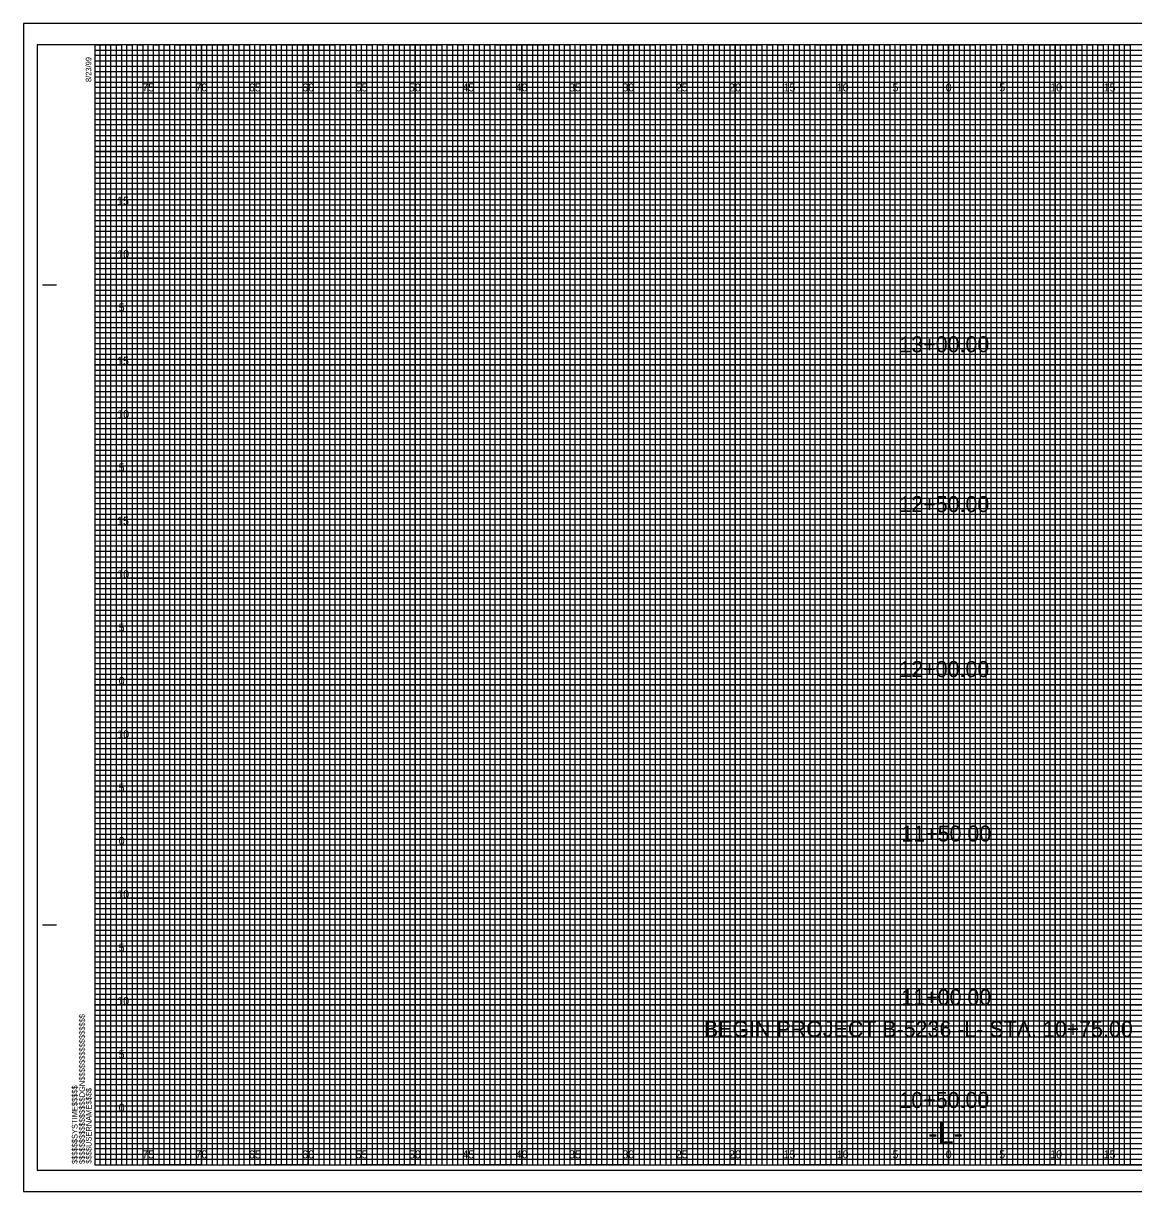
# Model space of a CAD drawing. Extents: x -7 to 162, y -2 to 107.
# Drawn here: x -6.7 to 97.3, y -2.5 to 107 of the extents above; entities that cross this region are included whole.
import ezdxf

# ---------------------------------------------------------------- set-up
doc = ezdxf.new("R2010")
doc.units = 0
for name, color, linetype in [('Prop XS Alignment Label', 7, 'Continuous'), ('Prop XS Elevation Labels', 7, 'Continuous'), ('Prop XS Offset Labels', 7, 'Continuous'), ('Prop XS Station Labels', 7, 'Continuous'), ('Sheet Cross Section CELL', 7, 'Continuous'), ('Sheet Cross Section Grid Major CELL', 7, 'Continuous'), ('Sheet Cross Section Grid Middle CELL', 7, 'Continuous'), ('Sheet Cross Section Grid Minor 1 CELL', 7, 'Continuous'), ('Sheet Cross Section Grid Minor 2 CELL', 7, 'Continuous'), ('Sheet Cutting Line CELL', 7, 'Continuous'), ('Sheet DOT Grid CELL', 7, 'Continuous'), ('Sheet Plot Border Inside CELL', 7, 'Continuous'), ('Sheet Plot Border Outside CELL', 7, 'Continuous')]:
    doc.layers.add(name, color=color, linetype=linetype)

msp = doc.modelspace()

# ---------------------------------------------------------------- linework, layer by layer
at = {"layer": 'Sheet Cross Section CELL'}
for p, q in [((-4.9, 82.5), (-3.65, 82.5)), ((-4.85, 82.5), (-3.6, 82.5)), ((-4.9, 22.5), (-3.65, 22.5)), ((-4.85, 22.5), (-3.6, 22.5)), ((0, 0), (0, 0)), ((0, 0), (0, 0)), ((0, 0), (0, 0)), ((0, 0), (0, 0)), ((0, 0), (0, 0)), ((0, 0), (0, 0)), ((0, 0), (0, 0))]:
    msp.add_line(p, q, dxfattribs=at)
msp.add_lwpolyline([(160, 105), (0, 105), (0, 0), (160, 0)], close=True, dxfattribs=at)
at = {"layer": 'Sheet Cross Section Grid Major CELL'}
for p, q in [((5, 105), (0, 105)), ((5, 0), (5, 105)), ((15, 105), (10, 105)), ((10, 105), (10, 0)), ((15, 0), (15, 105)), ((25, 105), (20, 105)), ((20, 105), (20, 0)), ((25, 0), (25, 105)), ((35, 105), (30, 105)), ((30, 105), (30, 0)), ((35, 0), (35, 105)), ((45, 105), (40, 105)), ((40, 105), (40, 0)), ((45, 0), (45, 105)), ((55, 105), (50, 105)), ((50, 105), (50, 0)), ((55, 0), (55, 105)), ((65, 105), (60, 105)), ((60, 105), (60, 0)), ((65, 0), (65, 105)), ((75, 105), (70, 105)), ((70, 105), (70, 0)), ((75, 0), (75, 105)), ((85, 105), (80, 105)), ((80, 105), (80, 0)), ((85, 0), (85, 105)), ((95, 105), (90, 105)), ((90, 105), (90, 0)), ((95, 0), (95, 105)), ((10, 0), (5, 0)), ((20, 0), (15, 0)), ((30, 0), (25, 0)), ((40, 0), (35, 0)), ((50, 0), (45, 0)), ((60, 0), (55, 0)), ((70, 0), (65, 0)), ((80, 0), (75, 0)), ((90, 0), (85, 0)), ((100, 0), (95, 0))]:
    msp.add_line(p, q, dxfattribs=at)
for points in [[(0, 100), (160, 100), (160, 95), (0, 95)], [(0, 90), (160, 90), (160, 85), (0, 85)], [(0, 80), (160, 80), (160, 75), (0, 75)], [(0, 70), (160, 70), (160, 65), (0, 65)], [(0, 60), (160, 60), (160, 55), (0, 55)], [(0, 50), (160, 50), (160, 45), (0, 45)], [(0, 40), (160, 40), (160, 35), (0, 35)], [(0, 30), (160, 30), (160, 25), (0, 25)], [(0, 20), (160, 20), (160, 15), (0, 15)], [(0, 10), (160, 10), (160, 5), (0, 5)]]:
    msp.add_lwpolyline(points, dxfattribs=at)
at = {"layer": 'Sheet Cross Section Grid Middle CELL'}
for points in [[(0, 105), (2.5, 105), (2.5, 0), (7.5, 0), (7.5, 105), (12.5, 105), (12.5, 0), (17.5, 0), (17.5, 105), (22.5, 105), (22.5, 0), (27.5, 0), (27.5, 105), (32.5, 105), (32.5, 0), (37.5, 0), (37.5, 105), (42.5, 105), (42.5, 0), (47.5, 0), (47.5, 105), (52.5, 105), (52.5, 0), (57.5, 0), (57.5, 105), (62.5, 105), (62.5, 0), (67.5, 0), (67.5, 105), (72.5, 105), (72.5, 0), (77.5, 0), (77.5, 105), (82.5, 105), (82.5, 0), (87.5, 0), (87.5, 105), (92.5, 105), (92.5, 0), (97.5, 0)], [(0, 102.5), (137.5, 102.5)], [(0, 92.5), (160, 92.5), (160, 97.5), (0, 97.5)], [(0, 82.5), (160, 82.5), (160, 87.5), (0, 87.5)], [(0, 72.5), (160, 72.5), (160, 77.5), (0, 77.5)], [(0, 62.5), (160, 62.5), (160, 67.5), (0, 67.5)], [(0, 52.5), (160, 52.5), (160, 57.5), (0, 57.5)], [(0, 42.5), (160, 42.5), (160, 47.5), (0, 47.5)], [(0, 32.5), (160, 32.5), (160, 37.5), (0, 37.5)], [(0, 22.5), (160, 22.5), (160, 27.5), (0, 27.5)], [(0, 12.5), (160, 12.5), (160, 17.5), (0, 17.5)], [(0, 2.5), (160, 2.5), (160, 7.5), (0, 7.5)]]:
    msp.add_lwpolyline(points, dxfattribs=at)
at = {"layer": 'Sheet Cross Section Grid Minor 1 CELL'}
for p, q in [((0, 104.5), (130, 104.5)), ((130, 103.99), (0, 103.99)), ((0, 103.99), (0, 103.5)), ((0, 103.5), (130, 103.5)), ((130, 102.95), (0, 102.95)), ((0, 102.95), (0, 102)), ((0, 102), (160, 102))]:
    msp.add_line(p, q, dxfattribs=at)
for points in [[(0, 101.5), (135, 101.5), (160, 101.5), (160, 101), (0, 101)], [(0, 100.5), (160, 100.5), (160, 99.5), (0, 99.5)], [(0, 99), (160, 99), (160, 98.5), (0, 98.49)], [(0, 98), (160, 98), (160, 97), (0, 97)], [(0, 96.5), (160, 96.5), (160, 96), (0, 96)], [(0, 95.5), (160, 95.5), (160, 94.5), (0, 94.5)], [(0, 94), (160, 94), (160, 93.5), (0, 93.5)], [(0, 93), (160, 93), (160, 92), (0, 92)], [(0, 91.5), (160, 91.5), (160, 91), (0, 91)], [(0, 90.5), (160, 90.5), (160, 89.5), (0, 89.5)], [(0, 89), (160, 89), (160, 88.5), (0, 88.5)], [(0, 88), (160, 88), (160, 86.98), (160, 86.5), (160, 86), (0, 86)], [(0, 87), (160, 87), (160, 86.5), (0, 86.5)], [(0, 85.5), (160, 85.5), (160, 84.5), (0, 84.52)], [(0, 84.52), (160, 84.5), (160, 84), (0, 84)], [(0, 83.5), (160, 83.5), (160, 83), (0, 83)], [(0, 82), (160, 82), (160, 81.5), (0, 81.5)], [(0, 81), (160, 81), (160, 80.5), (0, 80.5)], [(-0.04, 79.45), (160, 79.45), (160, 78.94), (-0.04, 78.94)], [(0, 78.5), (160, 78.5), (160, 78), (0, 78)], [(0, 77), (160, 77), (160, 76.5), (0, 76.5)], [(0, 76), (160, 76), (160, 75.5), (0, 75.5)], [(0, 74.5), (160, 74.5), (160, 74), (0, 74)], [(0, 73.5), (160, 73.5), (160, 73), (0, 73)], [(0, 72), (160, 72), (160, 71.5), (0, 71.5)], [(0, 71), (160, 71), (160, 70.5), (0, 70.5)], [(0, 69.5), (160, 69.5), (160, 68.99), (0, 69)], [(0, 68.5), (160, 68.5), (160, 68), (0, 68)], [(0, 67), (160, 67), (160, 66.5), (0, 66.5)], [(0, 66), (160, 66), (160, 65.5), (0, 65.5)], [(0, 64.5), (160, 64.5), (160, 64), (0, 64)], [(0, 63.5), (160, 63.5), (160, 63), (0, 63)], [(0, 62), (160, 62), (160, 61.5), (0, 61.5)], [(0, 61), (160, 61), (160, 60.5), (0, 60.5)], [(0, 59.5), (160, 59.5), (160, 59), (0, 59)], [(0, 58.5), (160.03, 58.45), (160, 58), (0, 58)], [(0, 57), (160, 57), (160, 56.5), (0, 56.5)], [(0, 56), (160, 56), (160, 55.5), (0, 55.5)], [(0, 54.5), (160, 54.5), (160, 54), (0, 54)], [(0, 53.5), (160, 53.5), (160, 53), (0, 53)], [(0, 52), (160, 52), (160, 51.5), (0, 51.5)], [(0, 51), (160, 51), (160, 50.5), (0, 50.5)], [(0, 49.5), (160, 49.5), (160, 49), (0, 49)], [(0, 48.5), (160, 48.5), (160, 48), (0, 48)], [(0, 47), (160, 47), (160, 46.5), (0, 46.5)], [(0, 46), (160, 46), (160, 45.5), (0, 45.5)], [(0, 44.5), (160, 44.5), (160, 44), (0, 44)], [(0, 43.5), (160, 43.5), (160, 43), (0, 43)], [(0, 42), (160, 42), (160, 41.5), (0, 41.5)], [(0, 41), (160, 41), (160, 40.5), (0, 40.5)], [(0, 39.5), (160, 39.5), (160, 38.99), (0, 39)], [(0, 38.5), (160, 38.5), (160, 38), (0, 38)], [(0, 37), (160, 37), (160, 36.5), (0, 36.5)], [(0, 36), (160, 36), (160, 35.5), (0, 35.5)], [(0, 34.5), (160, 34.5), (160, 34), (0, 34)], [(0, 33.5), (160, 33.5), (160, 33), (0, 33)], [(0, 32), (160, 32), (160, 31.5), (0, 31.5)], [(0, 31), (160, 31), (160, 30.5), (0, 30.5)], [(0, 29.5), (160, 29.5), (160, 29), (0, 29)], [(0, 28.5), (160.03, 28.46), (160, 28), (0, 28)], [(0, 27), (160, 27), (160, 26.5), (0, 26.5)], [(0, 26), (160, 26), (160, 25.5), (0, 25.5)], [(0, 24.5), (160, 24.5), (160, 24), (0, 24)], [(0, 23.5), (160, 23.5), (160, 23), (0, 23)], [(0, 22), (160, 22), (160, 21.5), (0, 21.5)], [(0, 21), (160, 21), (160, 20.5), (0, 20.5)], [(0, 19.5), (160, 19.5), (160, 19), (0, 19)], [(0, 18.5), (160, 18.5), (160, 18), (0, 18)], [(0, 17), (160, 17), (160, 16.5), (0, 16.5)], [(0, 16), (160, 16), (160, 15.5), (0, 15.5)], [(0, 14.5), (160, 14.5), (160, 14), (0, 14)], [(0, 13.5), (160, 13.5), (160, 13), (0, 13)], [(0, 12), (160, 12), (160, 11.5), (0, 11.5)], [(0, 11), (160, 11), (160, 10.5), (0, 10.5)], [(0, 9.5), (160, 9.5), (160, 9), (0, 9)], [(0, 8.5), (160, 8.5), (160, 8), (0, 8)], [(0, 7), (160, 7), (160, 6.5), (0, 6.5)], [(0, 6), (160, 6), (160, 5.5), (0, 5.5)], [(0, 4.5), (160, 4.5), (160, 4), (0, 4)], [(0, 3.5), (160, 3.5), (160, 3), (0, 3)], [(0, 2), (160, 2), (160, 1.5), (0, 1.5)], [(0, 1), (160, 1), (160, 0.5), (0, 0.5)]]:
    msp.add_lwpolyline(points, dxfattribs=at)
at = {"layer": 'Sheet Cross Section Grid Minor 2 CELL'}
for points in [[(0, 0), (0.5, 0), (0.5, 105), (1, 105), (1, 0)], [(1, 0), (1.5, 0), (1.5, 105), (2, 105), (2, 0)], [(2.5, 0), (3, 0), (3, 105), (3.5, 105), (3.5, 0)], [(3.5, 0), (4, 0), (4, 105), (4.5, 105), (4.5, 0)], [(5, 0), (5.5, 0), (5.5, 105), (6, 105), (6, 0)], [(6, 0), (6.5, 0), (6.5, 105), (7, 105), (7, 0)], [(7.5, 0), (8, 0), (8, 105), (8.5, 105), (8.5, 0)], [(8.5, 0), (9, 0), (9, 105), (9.5, 105), (9.5, 0)], [(10, 0), (10.5, 0), (10.5, 105), (11, 105), (11, 0)], [(11, 0), (11.5, 0), (11.5, 105), (12, 105), (12, 0)], [(12.5, 0), (13, 0), (13, 105), (13.5, 105), (13.5, 0)], [(13.5, 0), (14, 0), (14, 105), (14.5, 105), (14.5, 0)], [(15, 0), (15.5, 0), (15.5, 105), (16, 105), (16, 0)], [(16, 0), (16.5, 0), (16.5, 105), (17, 105), (17, 0)], [(17.5, 0), (18, 0), (18, 105), (18.5, 105), (18.5, 0)], [(18.5, 0), (19, 0), (19, 105), (19.5, 105), (19.5, 0)], [(20, 0), (20.5, 0), (20.5, 105), (21, 105), (21, 0)], [(21, 0), (21.5, 0), (21.5, 105), (22, 105), (22, 0)], [(22.5, 0), (23, 0), (23, 105), (23.5, 105), (23.5, 0)], [(23.5, 0), (24, 0), (24, 105), (24.5, 105), (24.5, 0)], [(25, 0), (25.5, 0), (25.5, 105), (26, 105), (26, 0)], [(26, 0), (26.5, 0), (26.5, 105), (27, 105), (27, 0)], [(27.5, 0), (28, 0), (28, 105), (28.5, 105), (28.5, 0)], [(28.5, 0), (29, 0), (29, 105), (29.5, 105), (29.5, 0)], [(30, 0), (30.5, 0), (30.5, 105), (31, 105), (31, 0)], [(31, 0), (31.5, 0), (31.5, 105), (32, 105), (32, 0)], [(32.5, 0), (33, 0), (33, 105), (33.5, 105), (33.5, 0)], [(33.5, 0), (34, 0), (34, 105), (34.5, 105), (34.5, 0)], [(35, 0), (35.5, 0), (35.5, 105), (36, 105), (36, 0)], [(36, 0), (36.5, 0), (36.5, 105), (37, 105), (37, 0)], [(37.5, 0), (38, 0), (38, 105), (38.5, 105), (38.5, 0)], [(38.5, 0), (39, 0), (39, 105), (39.5, 105), (39.5, 0)], [(40, 0), (40.5, 0), (40.5, 105), (41, 105), (41, 0)], [(41, 0), (41.5, 0), (41.5, 105), (42, 105), (42, 0)], [(42.5, 0), (43, 0), (43, 105), (43.5, 105), (43.5, 0)], [(43.5, 0), (44, 0), (44, 105), (44.5, 105), (44.5, 0)], [(45, 0), (45.5, 0), (45.5, 105), (46, 105), (46, 0)], [(46, 0), (46.5, 0), (46.5, 105), (47, 105), (47, 0)], [(47.5, 0), (48, 0), (48, 105), (48.5, 105), (48.5, 0)], [(48.5, 0), (49, 0), (49, 105), (49.5, 105), (49.5, 0)], [(50, 0), (50.5, 0), (50.5, 105), (51, 105), (51, 0)], [(51, 0), (51.5, 0), (51.5, 105), (52, 105), (52, 0)], [(52.5, 0), (53, 0), (53, 105), (53.5, 105), (53.5, 0)], [(53.5, 0), (54, 0), (54, 105), (54.5, 105), (54.5, 0)], [(55, 0), (55.5, 0), (55.5, 105), (56, 105), (56, 0)], [(56, 0), (56.5, 0), (56.5, 105), (57, 105), (57, 0)], [(57.5, 0), (58, 0), (58, 105), (58.5, 105), (58.5, 0)], [(58.5, 0), (59, 0), (59, 105), (59.5, 105), (59.5, 0)], [(60, 0), (60.5, 0), (60.5, 105), (61, 105), (61, 0)], [(61, 0), (61.5, 0), (61.5, 105), (62, 105), (62, 0)], [(62.5, 0), (63, 0), (63, 105), (63.5, 105), (63.5, 0)], [(63.5, 0), (64, 0), (64, 105), (64.5, 105), (64.5, 0)], [(65, 0), (65.5, 0), (65.5, 105), (66, 105), (66, 0)], [(66, 0), (66.5, 0), (66.5, 105), (67, 105), (67, 0)], [(67.5, 0), (68, 0), (68, 105), (68.5, 105), (68.5, 0)], [(68.5, 0), (69, 0), (69, 105), (69.5, 105), (69.5, 0)], [(70, 0), (70.5, 0), (70.5, 105), (71, 105), (71, 0)], [(71, 0), (71.5, 0), (71.5, 105), (72, 105), (72, 0)], [(72.5, 0), (73, 0), (73, 105), (73.5, 105), (73.5, 0)], [(73.5, 0), (74, 0), (74, 105), (74.5, 105), (74.5, 0)], [(75, 0), (75.5, 0), (75.5, 105), (76, 105), (76, 0)], [(76, 0), (76.5, 0), (76.5, 105), (77, 105), (77, 0)], [(77.5, 0), (78, 0), (78, 105), (78.5, 105), (78.5, 0)], [(78.5, 0), (79, 0), (79, 105), (79.5, 105), (79.5, 0)], [(80, 0), (80.5, 0), (80.5, 105), (81, 105), (81, 0)], [(81, 0), (81.5, 0), (81.5, 105), (82, 105), (82, 0)], [(82.5, 0), (83, 0), (83, 105), (83.5, 105), (83.5, 0)], [(83.5, 0), (84, 0), (84, 105), (84.5, 105), (84.5, 0)], [(85, 0), (85.5, 0), (85.5, 105), (86, 105), (86, 0)], [(86, 0), (86.5, 0), (86.5, 105), (87, 105), (87, 0)], [(87.5, 0), (88, 0), (88, 105), (88.5, 105), (88.5, 0)], [(88.5, 0), (89, 0), (89, 105), (89.5, 105), (89.5, 0)], [(90, 0), (90.5, 0), (90.5, 105), (91, 105), (91, 0)], [(91, 0), (91.5, 0), (91.5, 105), (92, 105), (92, 0)], [(92.5, 0), (93, 0), (93, 105), (93.5, 105), (93.5, 0)], [(93.5, 0), (94, 0), (94, 105), (94.5, 105), (94.5, 0)], [(95, 0), (95.5, 0), (95.5, 105), (96, 105), (96, 0)], [(96, 0), (96.5, 0), (96.5, 105), (97, 105), (97, 0)]]:
    msp.add_lwpolyline(points, dxfattribs=at)
at = {"layer": 'Sheet Cutting Line CELL'}
for p, q in [((161.65, 107), (-6.7, 107)), ((-6.7, 107), (-6.7, -2.5)), ((-6.7, -2.5), (161.65, -2.5))]:
    msp.add_line(p, q, dxfattribs=at)
at = {"layer": 'Sheet DOT Grid CELL'}
for p, q in [((5, 0), (5, 105)), ((10, 0), (10, 105)), ((15, 0), (15, 105)), ((20, 0), (20, 105)), ((25, 0), (25, 105)), ((30, 0), (30, 105)), ((35, 0), (35, 105)), ((40, 0), (40, 105)), ((45, 0), (45, 105)), ((50, 0), (50, 105)), ((55, 0), (55, 105)), ((60, 0), (60, 105)), ((65, 0), (65, 105)), ((70, 0), (70, 105)), ((75, 0), (75, 105)), ((80, 0), (80, 105)), ((85, 0), (85, 105)), ((90, 0), (90, 105)), ((95, 0), (95, 105)), ((0, 100), (160, 100)), ((0, 95), (160, 95)), ((0, 90), (160, 90)), ((0, 85), (160, 85)), ((0, 80), (160, 80)), ((0, 75), (160, 75)), ((0, 70), (160, 70)), ((0, 65), (160, 65)), ((0, 60), (160, 60)), ((0, 55), (160, 55)), ((0, 50), (160, 50)), ((0, 45), (160, 45)), ((0, 40), (160, 40)), ((0, 35), (160, 35)), ((0, 30), (160, 30)), ((0, 25), (160, 25)), ((0, 20), (160, 20)), ((0, 15), (160, 15)), ((0, 10), (160, 10)), ((0, 5), (160, 5))]:
    msp.add_line(p, q, dxfattribs=at)
at = {"layer": 'Sheet Plot Border Inside CELL'}
msp.add_lwpolyline([(-5.4, -0.5), (161.2, -0.5), (161.2, 105), (-5.4, 105)], close=True, dxfattribs=at)
at = {"layer": 'Sheet Plot Border Outside CELL'}
msp.add_lwpolyline([(-6.7, -2.5), (161.65, -2.5), (161.65, 107), (-6.7, 107)], close=True, dxfattribs=at)

# ---------------------------------------------------------------- texts
at = {"layer": 'Prop XS Alignment Label'}
msp.add_text('-L-', height=2, dxfattribs=at).set_placement((78.08, 2))
at = {"layer": 'Prop XS Elevation Labels'}
for s, p in [('15', (2.08, 90)), ('10', (2.09, 85)), ('5', (2.23, 80)), ('15', (2.08, 75)), ('10', (2.09, 70)), ('5', (2.23, 65)), ('15', (2.08, 60)), ('10', (2.09, 55)), ('5', (2.23, 50)), ('0', (2.23, 45)), ('10', (2.09, 40)), ('5', (2.23, 35)), ('0', (2.23, 30)), ('10', (2.09, 25)), ('5', (2.23, 20)), ('10', (2.09, 15)), ('5', (2.23, 10)), ('0', (2.23, 5))]:
    msp.add_text(s, height=0.75, dxfattribs=at).set_placement(p)
at = {"layer": 'Prop XS Offset Labels'}
for s, p in [('75', (4.44, 100.62)), ('70', (9.43, 100.62)), ('65', (14.44, 100.62)), ('60', (19.43, 100.62)), ('55', (24.44, 100.62)), ('50', (29.43, 100.62)), ('45', (34.44, 100.62)), ('40', (39.43, 100.62)), ('35', (44.44, 100.62)), ('30', (49.43, 100.62)), ('25', (54.44, 100.62)), ('20', (59.43, 100.62)), ('15', (64.53, 100.62)), ('10', (69.52, 100.62)), ('5', (74.74, 100.62)), ('0', (79.73, 100.62)), ('0', (79.73, 100.62)), ('5', (84.74, 100.62)), ('10', (89.52, 100.62)), ('15', (94.53, 100.62)), ('75', (4.44, 0.62)), ('70', (9.43, 0.62)), ('65', (14.44, 0.62)), ('60', (19.43, 0.62)), ('55', (24.44, 0.62)), ('50', (29.43, 0.62)), ('45', (34.44, 0.62)), ('40', (39.43, 0.62)), ('35', (44.44, 0.62)), ('30', (49.43, 0.62)), ('25', (54.44, 0.62)), ('20', (59.43, 0.62)), ('15', (64.53, 0.62)), ('10', (69.52, 0.62)), ('5', (74.74, 0.62)), ('0', (79.73, 0.62)), ('0', (79.73, 0.62)), ('5', (84.74, 0.62)), ('10', (89.52, 0.62)), ('15', (94.53, 0.62))]:
    msp.add_text(s, height=0.75, dxfattribs=at).set_placement(p)
at = {"layer": 'Prop XS Station Labels'}
for s, p in [('13+00.00', (75.39, 76.17)), ('12+50.00', (75.39, 61.19)), ('12+00.00', (75.39, 45.73)), ('11+50.00', (75.57, 30.31)), ('11+00.00', (75.57, 14.98)), ('BEGIN PROJECT B-5236 -L- STA. 10+75.00', (57.07, 11.99)), ('10+50.00', (75.39, 5.34))]:
    msp.add_text(s, height=1.5, dxfattribs=at).set_placement(p)
at = {"layer": 'Sheet Cross Section CELL'}
for s, p in [('8/23/99', (-0.33, 101.5)), ('$$$$$$$$$$$$$$$$DGN$$$$$$$$$$$$$$$$', (-0.94, 0.09)), ('$$$$$$SYSTIME$$$$$', (-1.63, 0.09)), ('$$$$USERNAME$$$$', (-0.31, 0.12))]:
    msp.add_text(s, height=0.525, rotation=90, dxfattribs=at).set_placement(p)

doc.saveas('drawing.dxf')
